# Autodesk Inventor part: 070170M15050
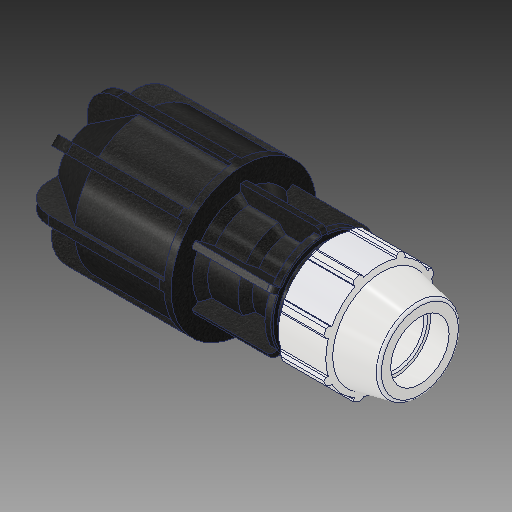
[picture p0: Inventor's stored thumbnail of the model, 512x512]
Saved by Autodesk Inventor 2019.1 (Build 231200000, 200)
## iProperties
Created: 2017-02
Part Number: 070170M15050
Material: PVC-Piping
Description: PLASSON PLASS4 COUPLING 1 1/2'' - 1.675
Document SubType Name: Modeling
Designer: KIM
Mass: 92.6774 g
Surface Area: 199.44 cm^2
Volume: 66.1981 cm^3
Density: 1.4 g/cm^3
Appearance: PTFE
Author: KIM
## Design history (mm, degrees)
derived "070170M0.ipt"
feature "Solid1::070170M0.ipt"
tag "TaggingFeature1"
body "Solid1"
other parameters: "d_" = 48.1, "E_" = 96.012, "A_" = 81, "l_" = 89.916, "d_1" = 42.545, "E_1" = 119.888, "l_1" = 124.968, "H_" = 270.002, "d106" = 60.24472, "d2" = 48.1, "d4" = 19.28586, "d5" = 31.4706, "d7" = 96.012, "d8" = 60.24472, "d9" = 11.57143, "d11" = 6.75005, "d12" = 76.8096, "d13" = 120 deg, "d14" = 67.34, "d15" = 12 deg, "d16" = 86.4108, "d18" = 2.405, "d19" = 35 deg, "d20" = 17.5 deg, "d21" = 89.29116, "d23" = 0, "d25" = 360 deg, "d27" = 1.92024, "d42" = 40.4622, "d43" = 2.88036, "d46" = 1.443, "d53" = 0.962, "d67" = 4.8006, "d70" = 43.29, "d71" = 89.916, "d74" = 180 deg, "d75" = 42.545, "d76" = 119.888, "d80" = 43.29, "d84" = 113.8936, "d85" = 135 deg, "d86" = 5.9944, "d89" = 5.9944, "d90" = 135 deg, "d94" = 5.9944, "d97" = 7.68096, "d98" = 0, "d100" = 360 deg, "d102" = 131.8768, "d103" = 23.9776, "d104" = 9.59104, "d105" = 0, "d110" = 124.968, "d112" = 162.0012, "d113" = 42.48912, "d114" = 108.0008, "d115" = 71.9328, "d116" = 162.0012, "d117" = 6.2484, "d118" = 48.006, "d119" = 4.8006, "d120" = 0, "d121" = 4.8006, "d123" = 360 deg
